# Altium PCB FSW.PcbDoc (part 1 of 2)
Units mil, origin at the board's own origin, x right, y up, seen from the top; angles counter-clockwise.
Board outline 4340.74 x 2765.94 mil, 4 copper layers (Top Layer, Layer 1, Layer 2, Bottom Layer), stack 63.43 mil thick; 152 components, 72 nets, 476 pads, 391 vias.
Unrouted connection lines stored in the file: 225.
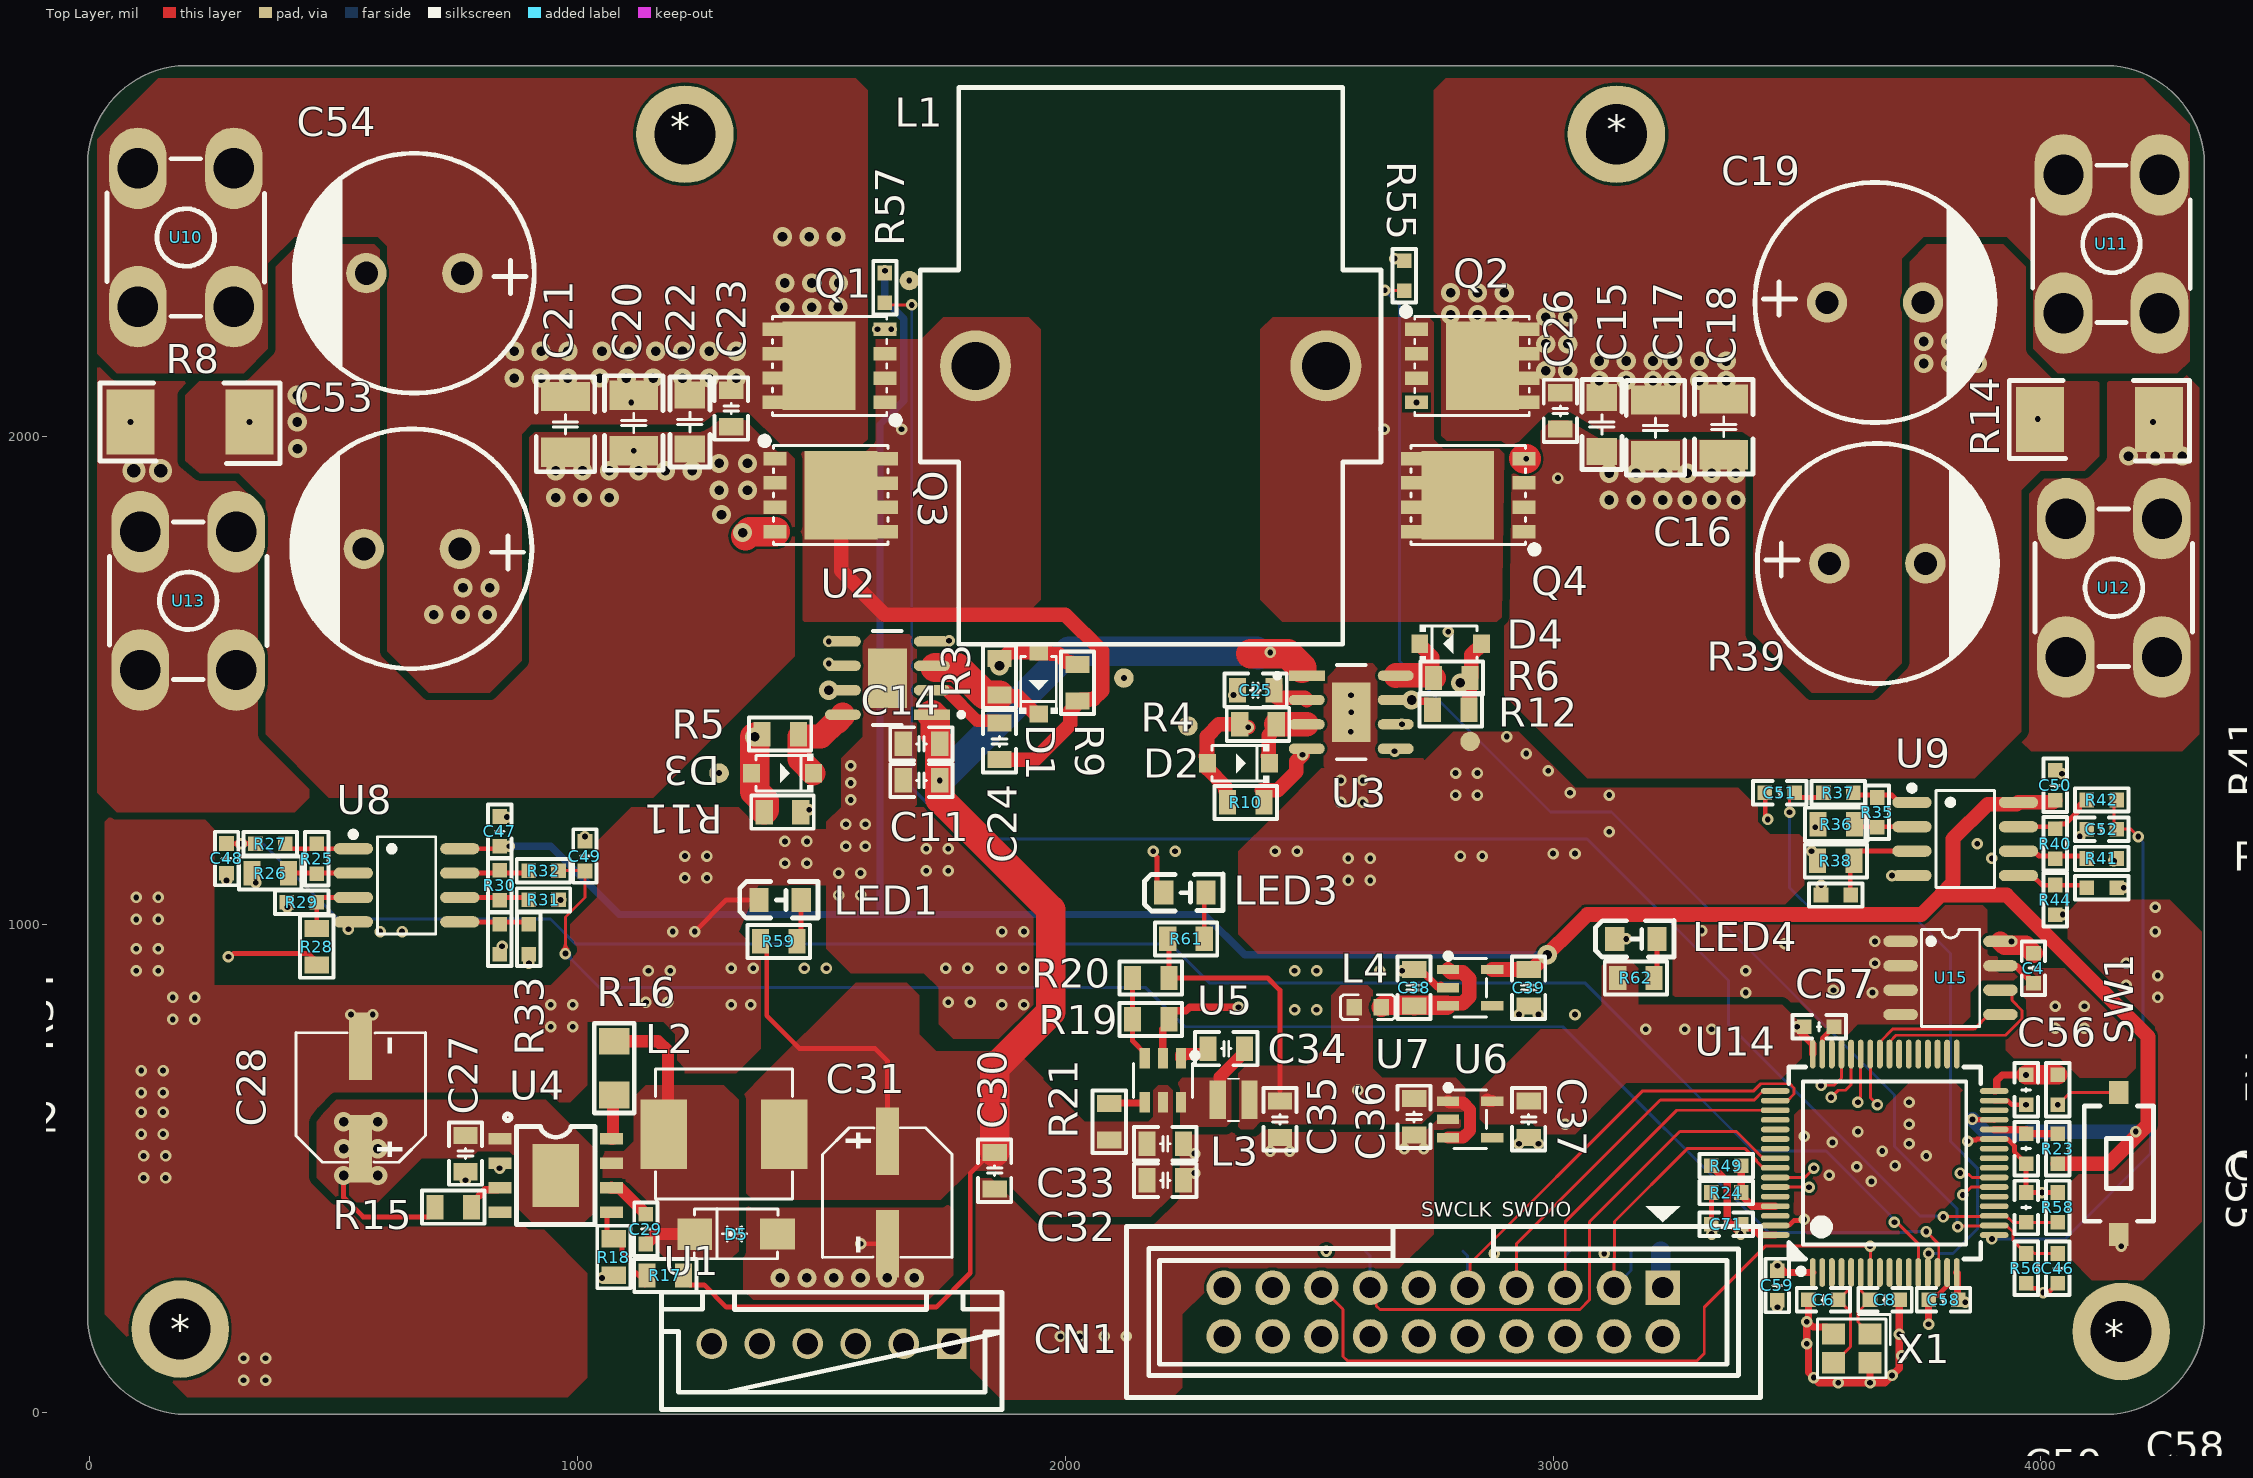
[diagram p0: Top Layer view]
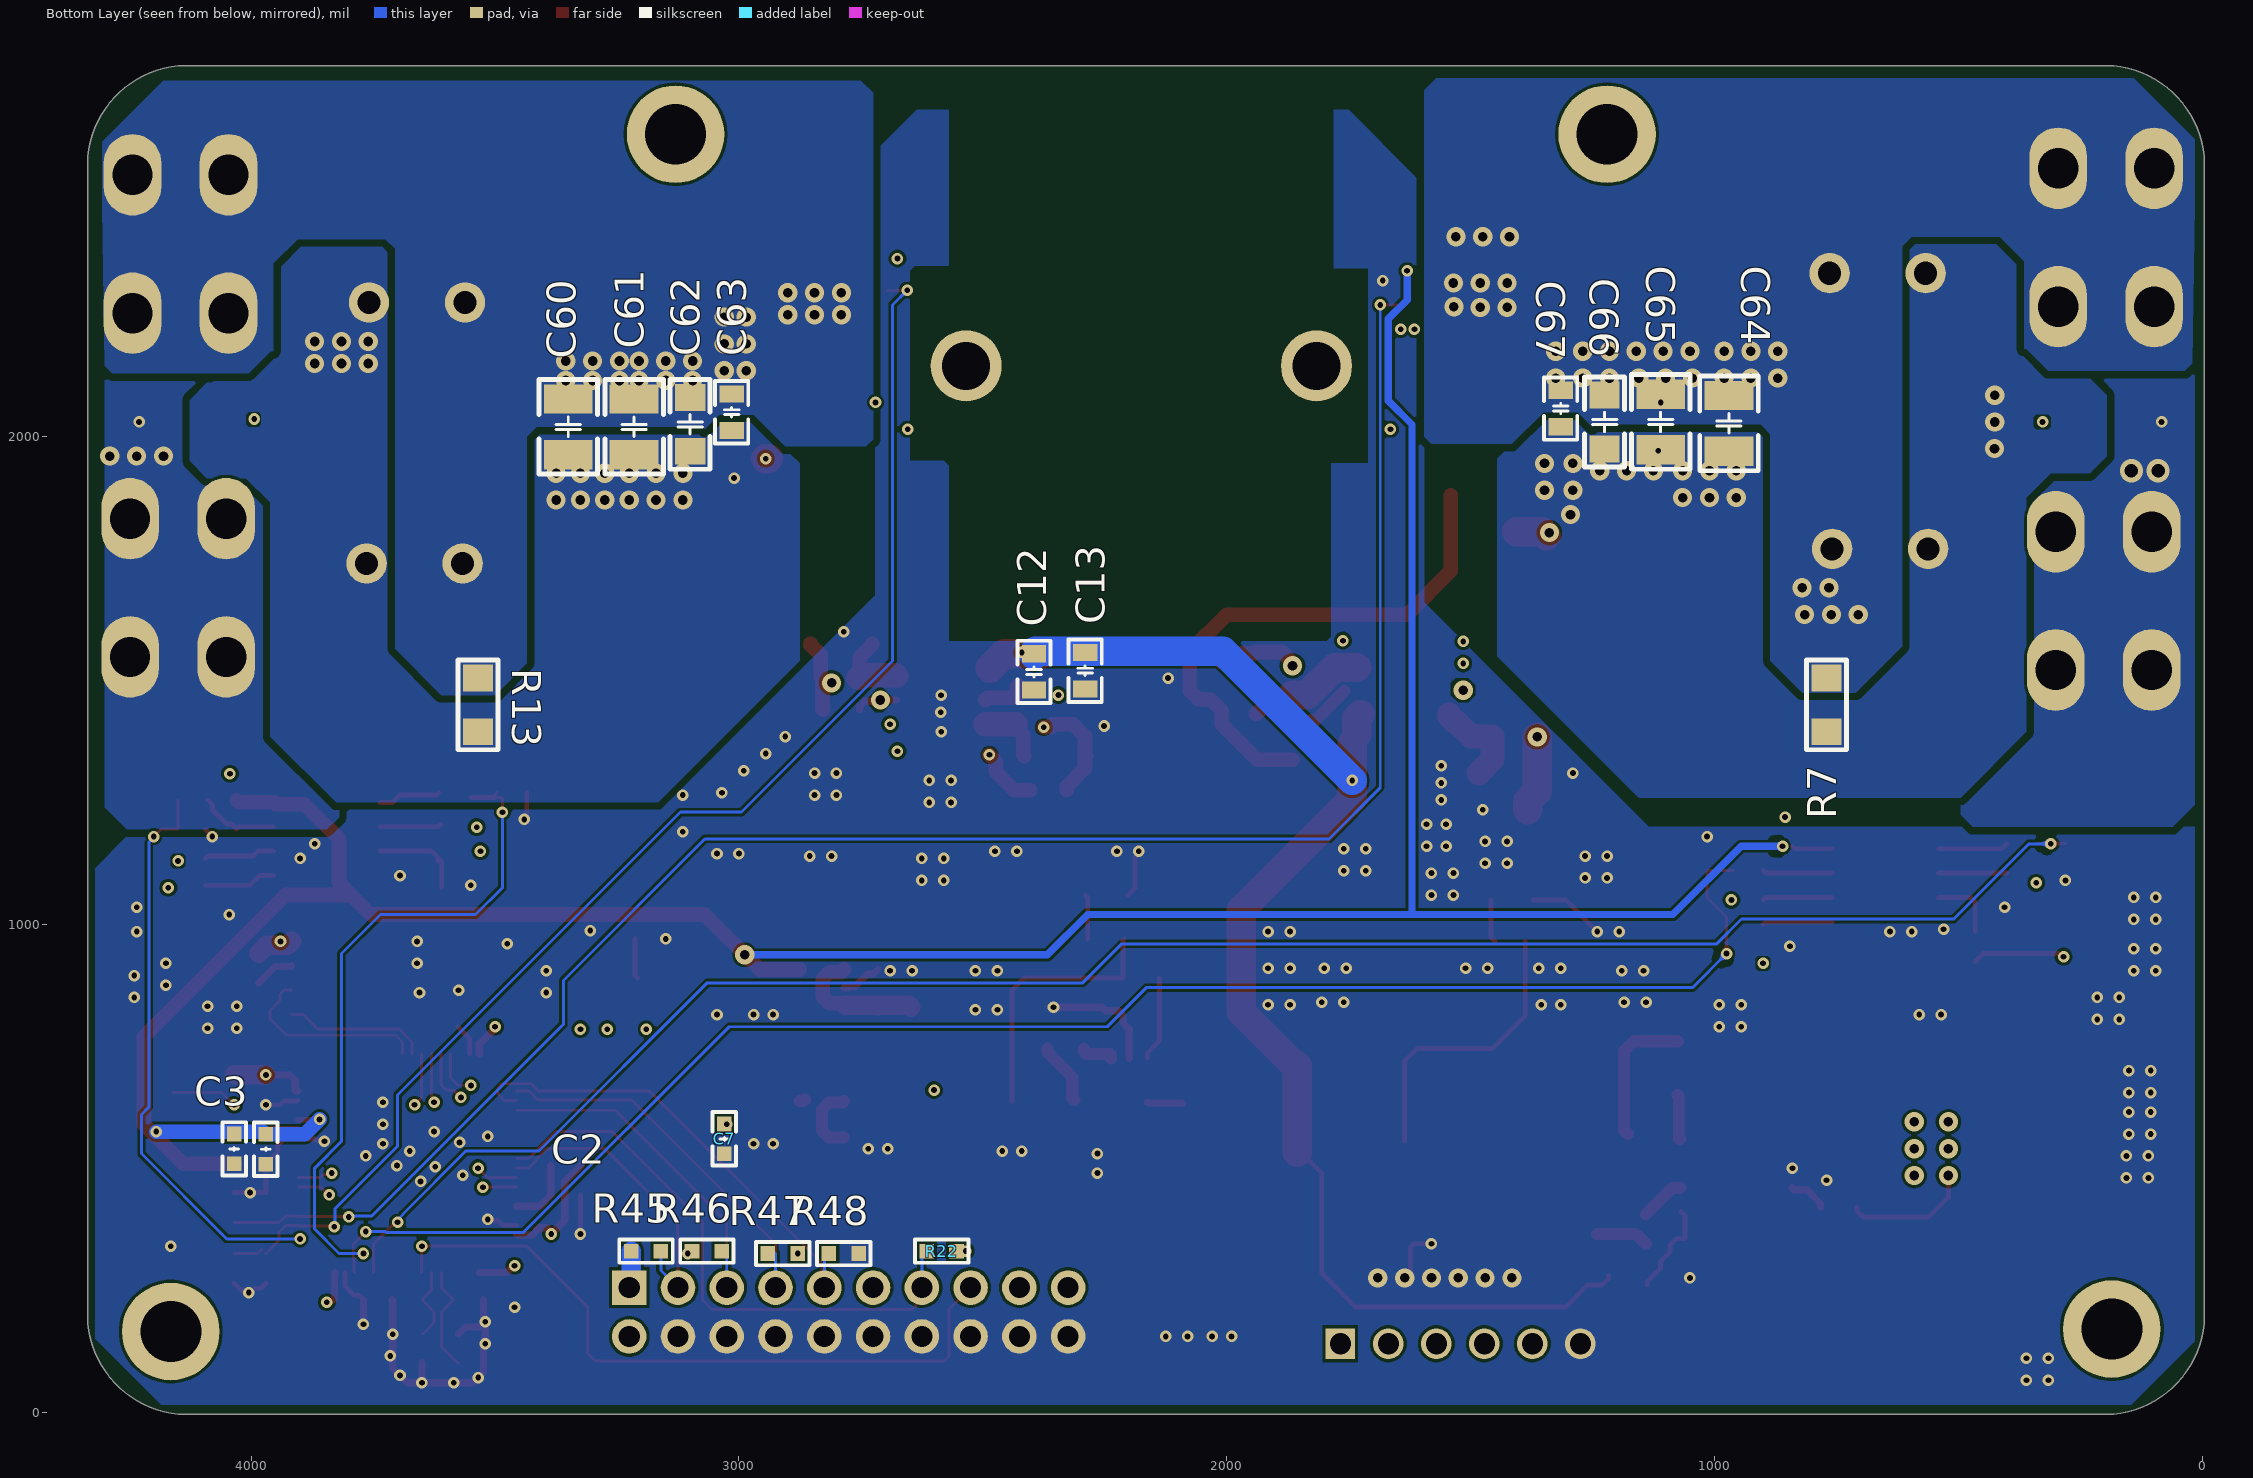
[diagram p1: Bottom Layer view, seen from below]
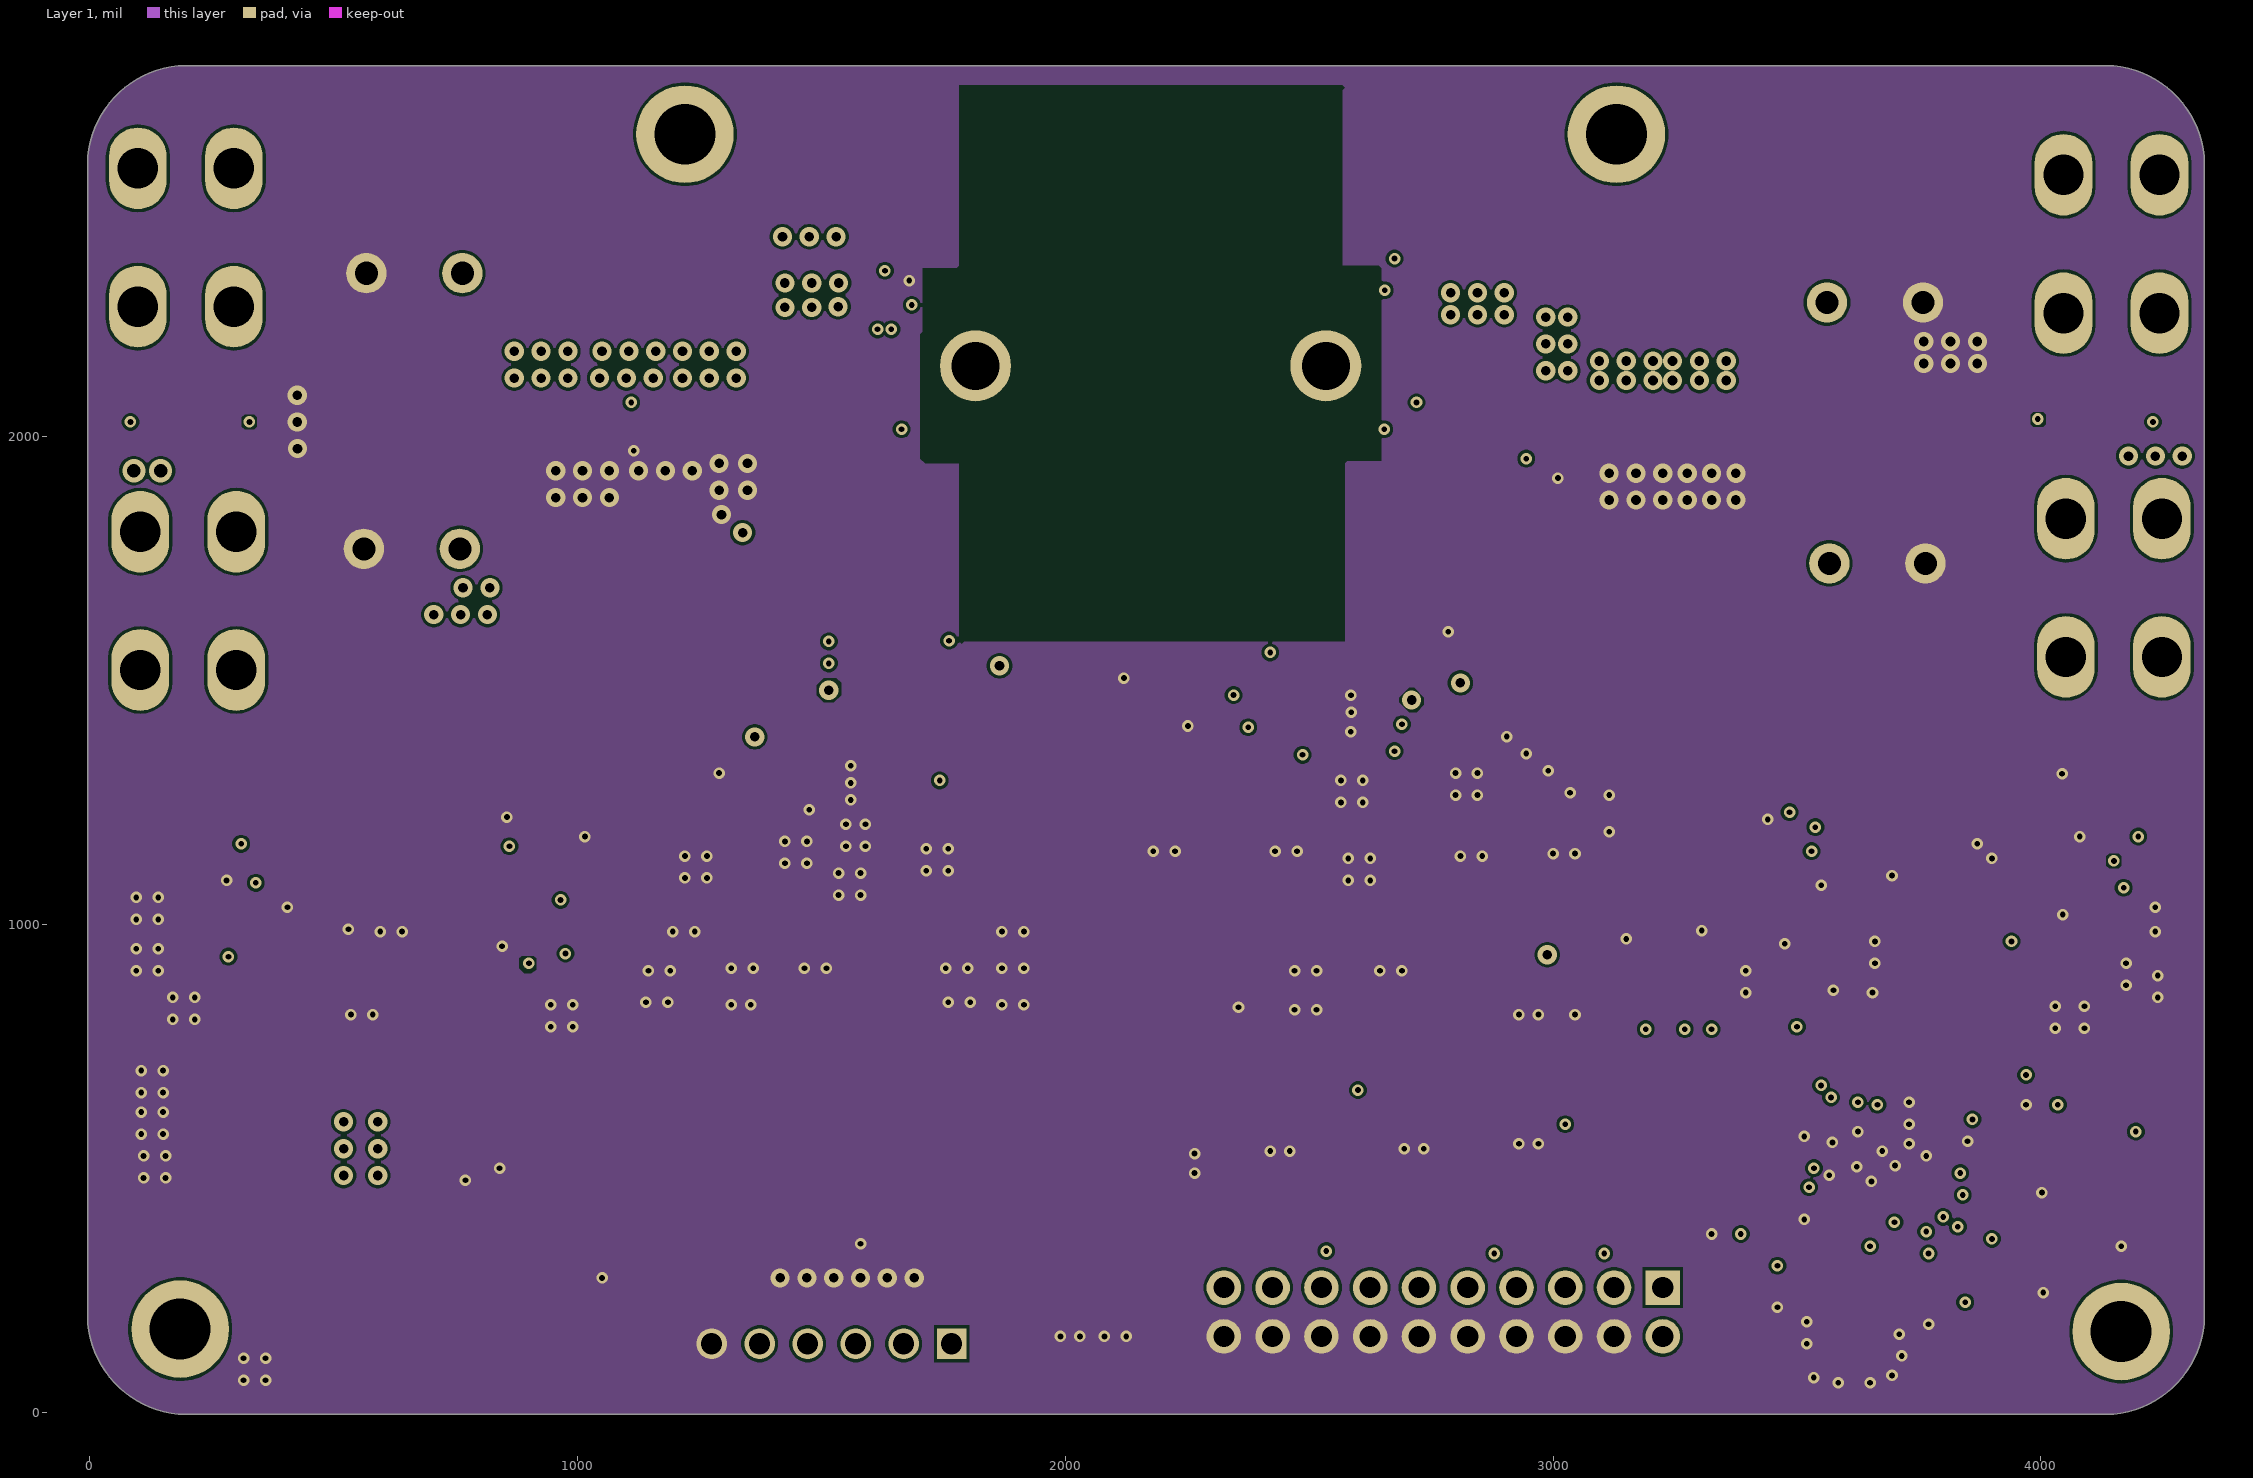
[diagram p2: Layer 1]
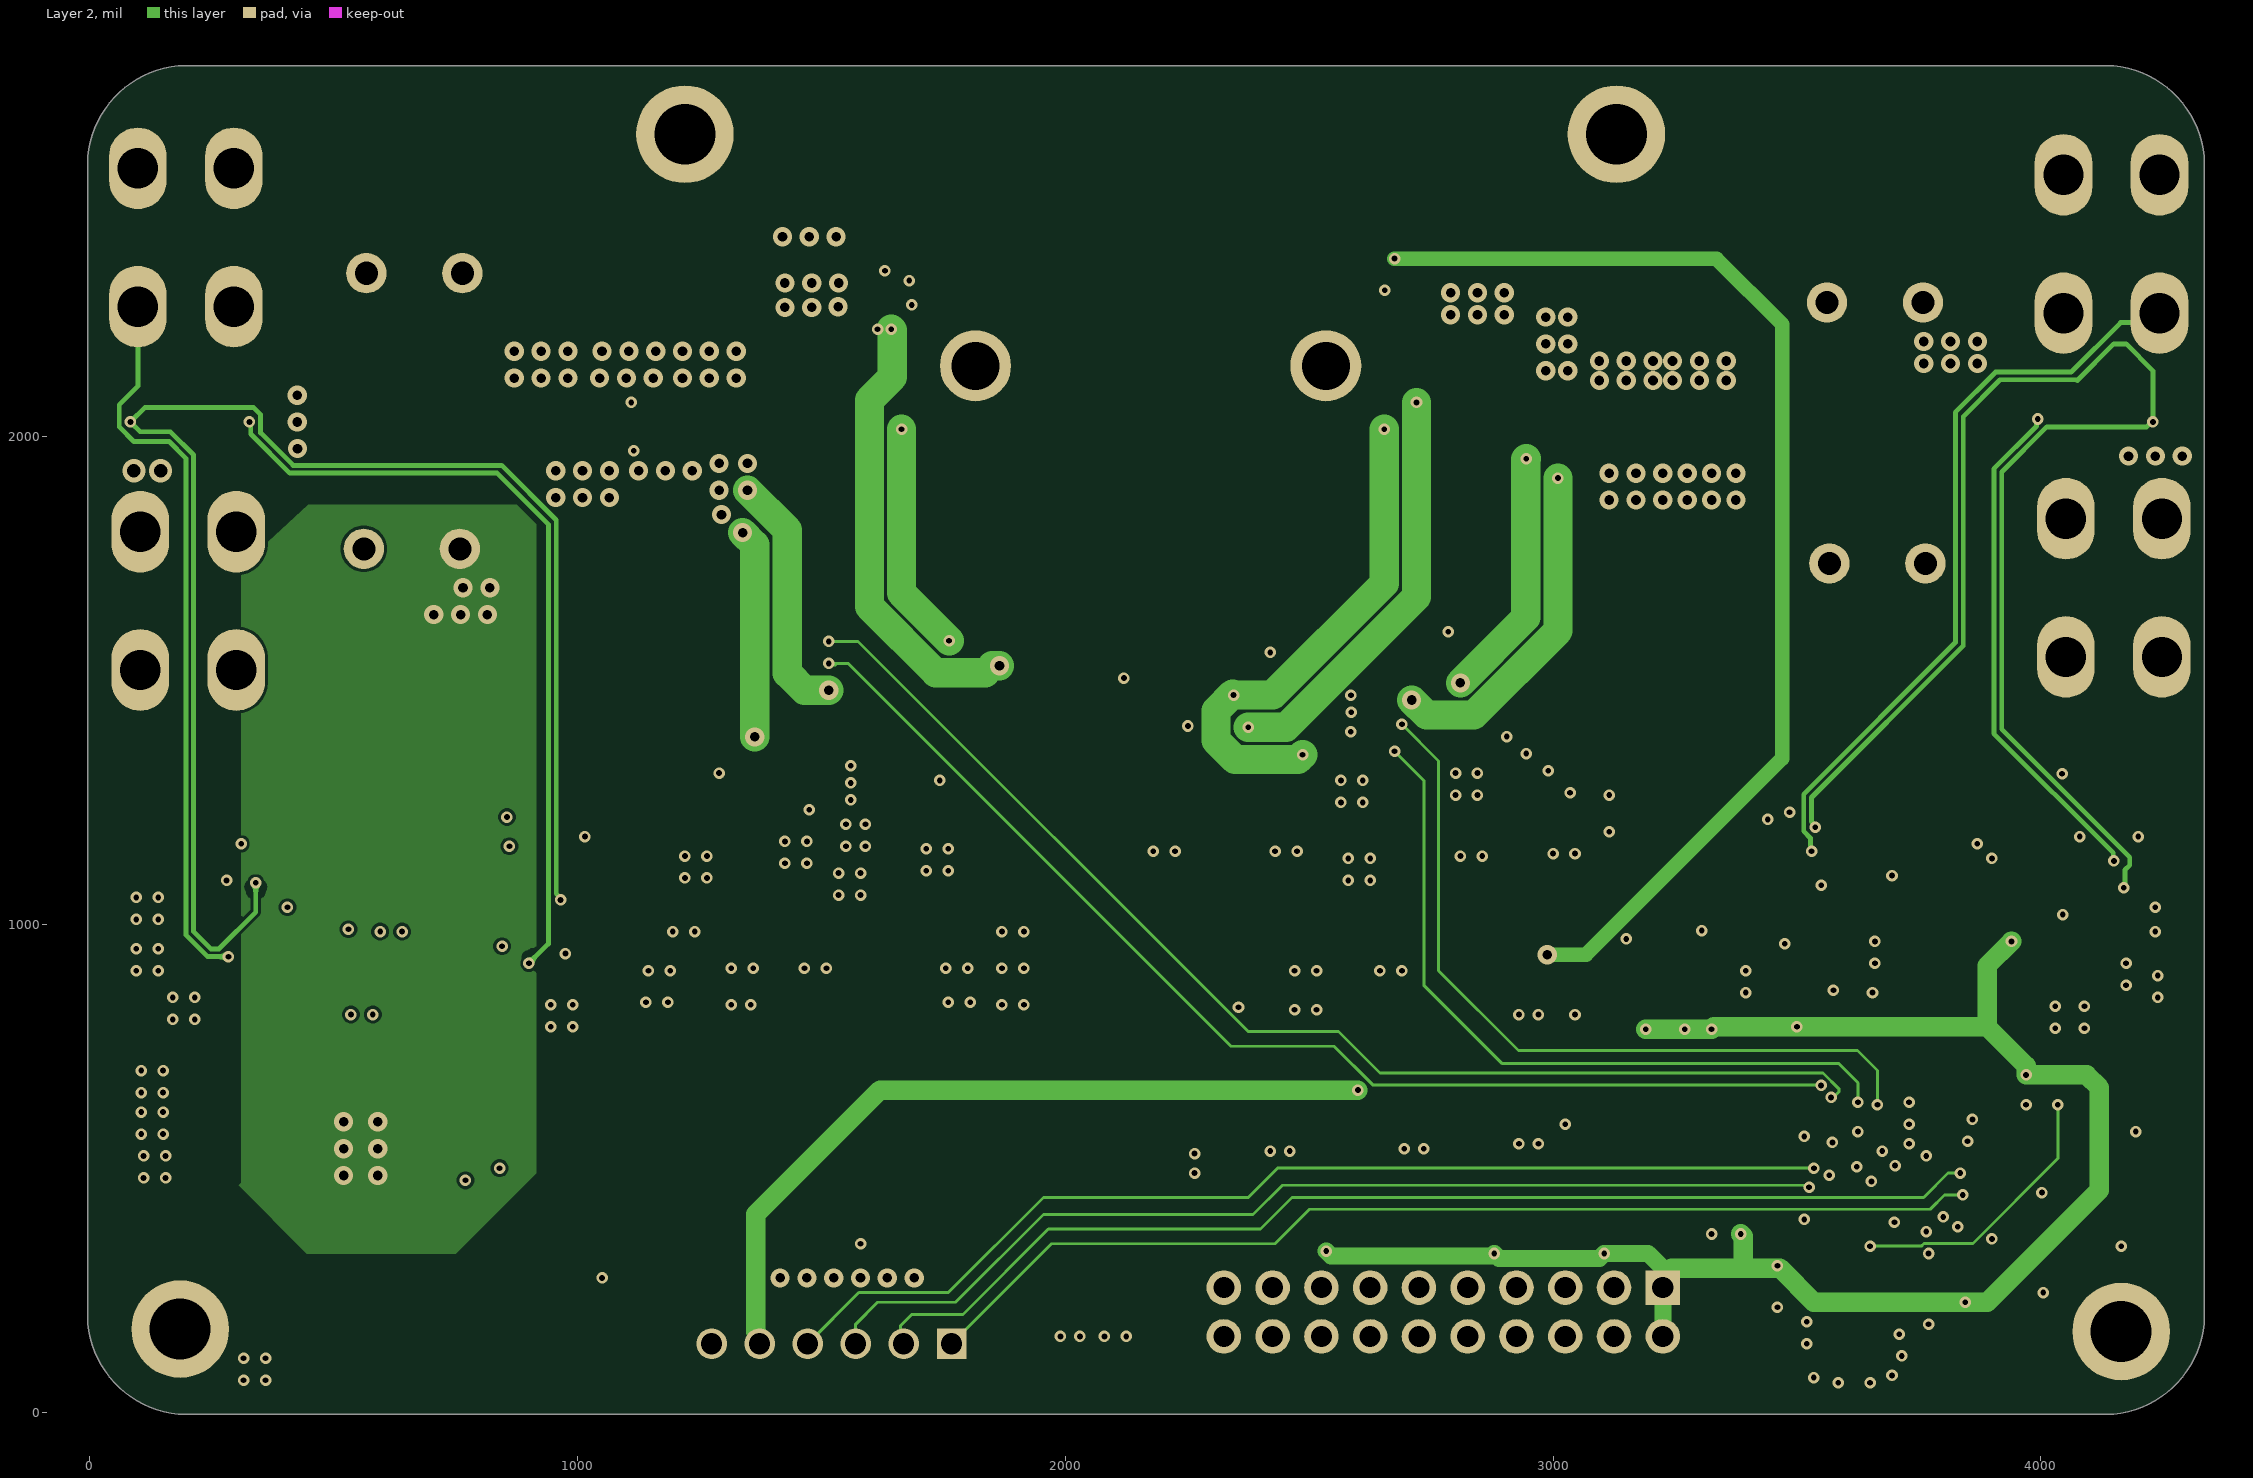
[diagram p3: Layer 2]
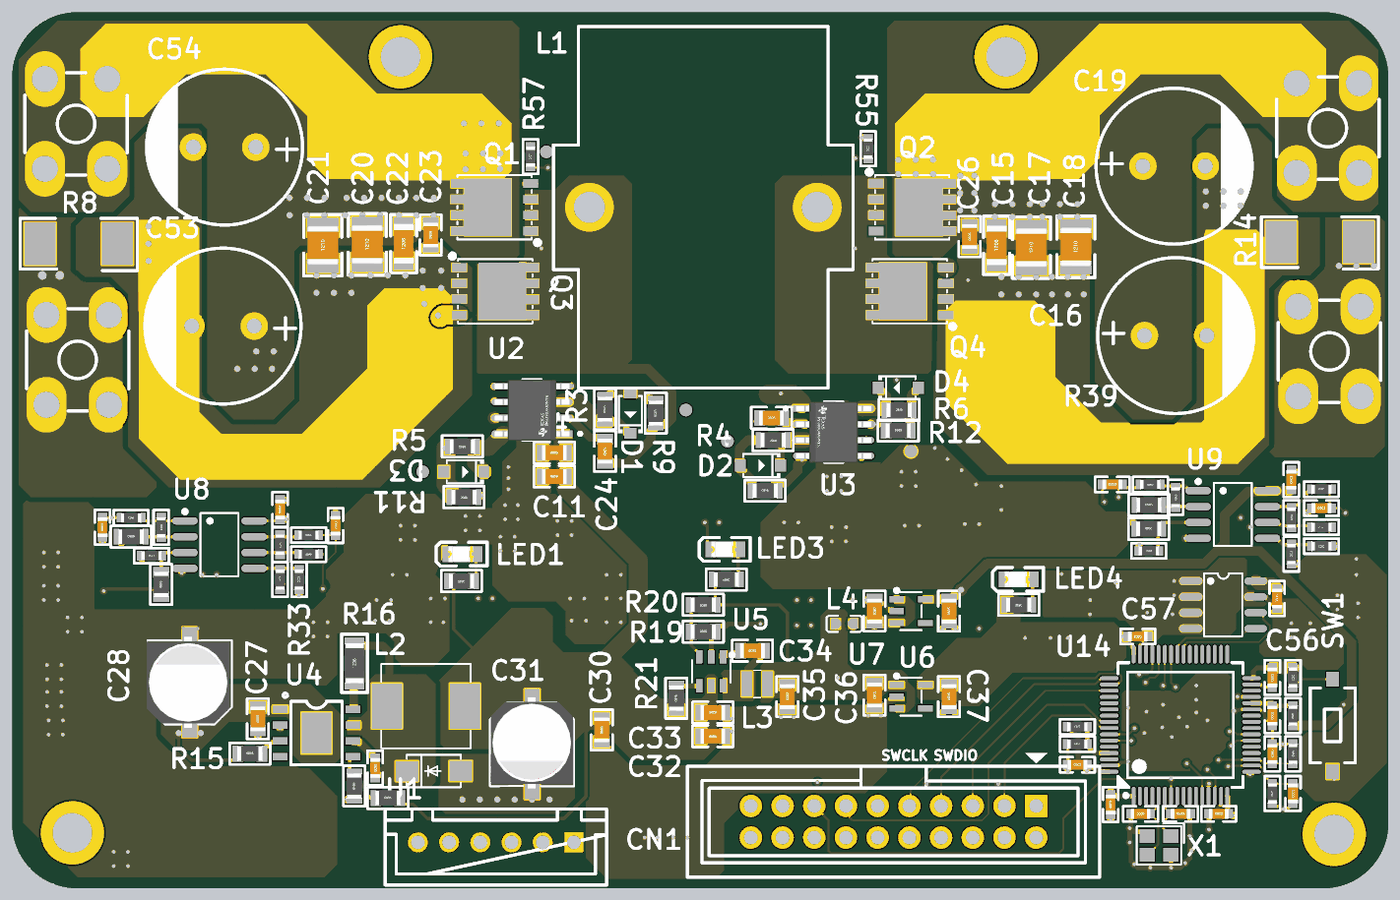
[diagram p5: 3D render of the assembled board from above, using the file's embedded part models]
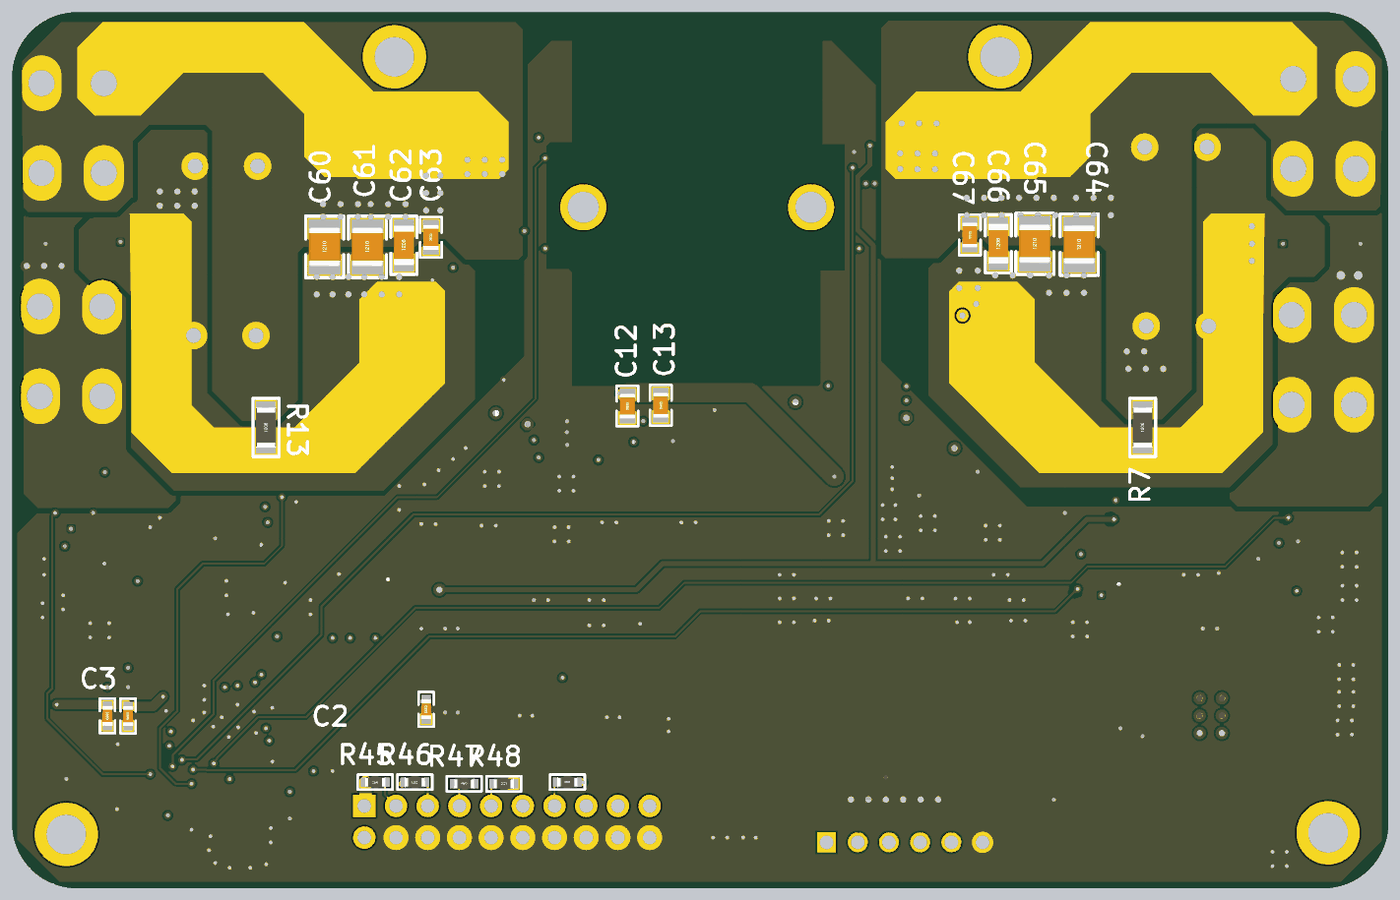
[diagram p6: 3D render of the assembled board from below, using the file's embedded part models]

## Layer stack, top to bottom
Top Solder: solder mask 0.4, Solder Resist, Dk 3.5
Top Layer: signal copper 1.4
Dielectric 2: prepreg 7.0866, PP-006, Dk 4.1
Layer 1: signal copper 1.378
Dielectric 1: dielectric 43.7008, FR-4, Dk 4.8
Layer 2: signal copper 1.378
Dielectric 3: prepreg 7.0866, PP-006, Dk 4.1
Bottom Layer: signal copper 1.4
Bottom Solder: solder mask 0.4, Solder Resist, Dk 3.5

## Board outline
196.27,-4.98 cw(c200,200) -4.98,196.27 -5.01,196.85 -5.01,2559.06 -4.98,2559.64 cw(c200,2555.91) 196.27,2760.89 196.85,2760.92 4133.86,2760.92 4134.44,2760.89 cw(c4130.71,2555.91) 4335.69,2559.64 4335.72,2559.06 4335.72,196.85 4335.69,196.27 cw(c4130.71,200) 4134.44,-4.98 4133.86,-5.01

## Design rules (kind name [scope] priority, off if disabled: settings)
Clearance [All] p1: gap=6 ignorepadtopadclearanceinfootprint=FALSE except(0: Arc-Hole Track-Hole SMDPad-Hole THPad-Hole Via-Hole Fill-Hole Poly-Hole Region-Hole Text-Hole; 10: Arc-Text Track-Text SMDPad-Text THPad-Text Via-Text Fill-Text Poly-Text Region-Text Text-Text; 15.75: Fill-Fill Fill-Poly Fill-Region Poly-Poly Poly-Region Region-Region)
HoleSize [All] p1: absolutevalues=TRUE maxlimit=3937.01 minlimit=1 maxpercent=80.000 minpercent=20.000
MinimumSolderMaskSliver [All] p1: minsoldermaskwidth=4
PolygonConnect [All] p1: connectstyle=Direct reliefconductorwidth=10 reliefentries=4 polygonreliefangle="90 Angle" airgapwidth=10
RoutingVias [All] p1: holewidth=11.81 width=23.62 viastyle="Through Hole" minholewidth=11.81 minwidth=23.62 maxholewidth=28 maxwidth=50
SilkToSolderMaskClearance [IsPad] p1: minsilkscreentomaskgap=4 clearancetoexposedcopper=TRUE
SolderMaskExpansion [All] p1: expansion=4 istentingtop=FALSE
Width [All] p1: maxlimit=100 minlimit=6 preferedwidth=10 minimp=50.000000 maximp=50.000000 favimp=50.000000
27 further rules are at their usual default settings.

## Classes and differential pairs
component class NTC: C46 C55 R55 R56 R57 R58
component class sense: C47 C48 C49 C50 C51 C52 R25 R26 R27 R28 R29 R30 R31 R32 R33 R34 R35 R36 R37 R38 R39 R40 R41 R42 R43 R44 U8 U9
component class "auxiliary power supply": +12v C27 C28 C29 C30 C31 C32 C33 C34 C35 C36 C37 C38 C39 D5 L2 L3 L4 LED1 LED3 LED4 R15 R16 R17 R18 R19 R20 R21 R59 R61 R62 U4 U5 U6 U7
component class power: C11 C12 C13 C14 C15 C16 C17 C18 C19 C20 C21 C22 C23 C24 C25 C26 C53 C54 C60 C61 C62 C63 C64 C65 C66 C67 D1 D2 D3 D4 L1 Q1 Q2 Q3 Q4 R3 R4 R5 R6 R7 R8 R9 R10 R11 R12 R13 R14 U2 U3 U10 U11 U12 U13
component class FSW: * C1 C2 C3 C4 C6 C7 C8 C56 C57 C58 C59 C71 CN1 R1 R22 R23 R24 R45 R46 R47 R48 R49 SW1 U1 U14 U15 X1

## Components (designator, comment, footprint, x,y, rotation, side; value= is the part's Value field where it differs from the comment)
* "M3" "M3 125X200" 3130,2620 r0 top
* "M3" "M3 125X200" 185,170 r0 top
* "M3" "M3 125X200" 1220,2620 r0 top
* "M3" "M3 125X200" 4165,165 r0 top
C1 "2.2uF" "C 0603_L" 3970,540 r90 top
C2 "100nF" "C 0603_L" 3970,538.82 r90 bottom
C3 "4.7uF" "C 0603_L" 4035,539.41 r90 bottom
C4 "100nF" "C 0603_L" 3985,910 r90 top
C6 "20pF" "C 0603_L" 3554.41,230 r0 top
C7 "4.7uF" "C 0603_L" 3030,560 r90 bottom
C8 "20pF" "C 0603_L" 3680.59,230 r0 top
C11 "10uF" "C 0805_L" 1705,1295 r0 top
C12 "100nF" "C 0805_L" 2395,1517.4 r90 bottom
C13 "10uF" "C 0805_L" 2290,1520 r90 bottom
C14 "100nF" "C 0805_L" 1705,1370 r0 top
C15 "1uF" "C 1206_L" 3100,2024.89 r90 top
C16 "100yxj220m12.5x25" CAP-TH_BD12.5-P5.00-D0.6-FD 3665,1740 r0 top value=220uF
C17 "4.7uF" "C 1210_L" 3210,2017.91 r90 top
C18 "4.7uF" "C 1210_L" 3350,2020 r90 top
C19 "100yxj220m12.5x25" CAP-TH_BD12.5-P5.00-D0.6-FD 3660,2275 r0 top value=220uF
C20 "4.7uF" "C 1210_L" 1115,2027.91 r90 top
C21 "4.7uF" "C 1210_L" 975,2025 r90 top
C22 "1uF" "C 1206_L" 1230,2029.89 r90 top
C23 "100nF" "C 0805_L" 1315,2057.6 r90 top
C24 "100nF" "C 0805_L" 1865,1375 r90 top
C25 "100nF" "C 0805_L" 2390,1480 r0 top
C26 "100nF" "C 0805_L" 3015,2052.6 r90 top
C27 "100nF" "C 0805_L" 770,530 r90 top
C28 "jvj100v22m6x8" CAP-SMD_BD6.3-L6.6-W6.6-LS7.3-FD-H7.7 555,645 r90 top value=22uF
C29 "100nF" "C 0603_L" 1140,375 r270 top
C30 "100nF" "C 0805_L" 1855,495 r90 top
C31 "ma25v220m6x8" CAP-SMD_BD6.3-L6.6-W6.6-LS7.3-FD 1635,450 r270 top value=220uF
C32 "4.7uF" "C 0805_L" 2205,550 r180 top
C33 "100nF" "C 0805_L" 2205,475 r180 top
C34 "100nF" "C 0805_L" 2330,745 r180 top
C35 "22uF" "C 0805_L" 2440,600 r270 top
C36 "4.7uF" "C 0805_L" 2715,605 r90 top
C37 "4.7uF" "C 0805_L" 2950,600 r90 top
C38 "4.7uF" "C 0805_L" 2715,870 r270 top
C39 "4.7uF" "C 0805_L" 2950,870 r90 top
C46 "100nF" "C 0603_L" 4035,294.41 r90 top
C47 "470nF" "C 0603_L" 840,1190.59 r90 top
C48 "330pF" "C 0603_L" 280,1135 r90 top
C49 "330pF" "C 0603_L" 1015,1140 r270 top
C50 "470nF" "C 0603_L" 4030,1285 r90 top
C51 "330pF" "C 0603_L" 3465,1270 r0 top
C52 "330pF" "C 0603_L" 4125,1195 r0 top
C53 "100yxj220m12.5x25" CAP-TH_BD12.5-P5.00-D0.6-FD 660,1770 r180 top value=220uF
C54 "100yxj220m12.5x25" CAP-TH_BD12.5-P5.00-D0.6-FD 665,2335 r180 top value=220uF
C55 "100nF" "C 0603_L" 3970,419.41 r270 top
C56 "100nF" "C 0603_L" 3970,660.59 r90 top
C57 "100nF" "C 0603_L" 3545.59,790 r180 top
C58 "100nF" "C 0603_L" 3800.59,230 r0 top
C59 "100nF" "C 0603_L" 3460,259.41 r90 top
C60 "4.7uF" "C 1210_L" 3350,2020 r90 bottom
C61 "4.7uF" "C 1210_L" 3215,2020 r90 bottom
C62 "1uF" "C 1206_L" 3100,2025 r90 bottom
C63 "100nF" "C 0805_L" 3015,2050 r90 bottom
C64 "4.7uF" "C 1210_L" 970,2027.09 r90 bottom
C65 "4.7uF" "C 1210_L" 1110,2030 r90 bottom
C66 "1uF" "C 1206_L" 1225,2030 r90 bottom
C67 "100nF" "C 0805_L" 1315,2057.6 r90 bottom
C71 "100nF" "C 0603_L" 3355,385 r0 top
CN1 "bh254v-20p" CONN-TH_20P-P2.54_BH254V-20P 2775,205 r180 top
D1 "1n4148w_c7420318" SOD-123_L2.7-W1.6-LS3.7-FD 1945,1495 r270 top
D2 "1n4148w_c7420318" SOD-123_L2.7-W1.6-LS3.7-FD 2355,1330 r0 top
D3 "1n4148w_c7420318" SOD-123_L2.7-W1.6-LS3.7-FD 1420,1310 r0 top
D4 "1n4148w_c7420318" SOD-123_L2.7-W1.6-LS3.7-FD 2790,1575 r180 top
D5 "ss310_c7420364" SMA_L4.3-W2.6-LS5.0-FD 1325,365 r180 top
L1 "fc-se2822-150m" IND-TH_L28.0-W23.0_FC-SE2822 2175,2145 r90 top value=15uH
L2 "fxl0630-470-m" IND-SMD_L7.0-W6.6_FXL0630 1300,570 r180 top value=47uH
L3 "ftc252010s4r7mbca" IND-SMD_L2.5-W2.0-VLS252012CX-150M 2345,640 r0 top value=4.7uH
L4 "gz1608d601tf" L0603 2620,830 r0 top
LED1 "ncd0805r1" LED0805-RD 1415,1050 r0 top
LED3 "ncd0805r1" LED0805-RD 2245,1065 r0 top
LED4 "ncd0805r1" LED0805-RD 3170,970 r0 top
Q1 "cjac80sn10" PDFN-8_L5.8-W5.0-P1.27-LS6.0-BL 1516.2,2145 r90 top
Q2 "cjac80sn10" PDFN-8_L5.8-W5.0-P1.27-LS6.0-BL 2834.2,2145 r270 top
Q3 "cjac80sn10" PDFN-8_L5.8-W5.0-P1.27-LS6.0-BL 1519.2,1880 r270 top
Q4 "cjac80sn10" PDFN-8_L5.8-W5.0-P1.27-LS6.0-BL 2825.8,1880 r90 top
R1 "10K" "R 0603_L" 4035,660.59 r270 top
R3 "10R" "R 0805_L" 1865,1507.4 r90 top
R4 "10R" "R 0805_L" 2395,1410 r180 top
R5 "10R" "R 0805_L" 1415,1390 r180 top
R6 "10R" "R 0805_L" 2792.4,1505 r0 top
R7 "10K" "R 1206_L" 770,1450 r90 bottom
R8 "hojlr2512-3w-5mr-1%" RES-SMD_L6.4-W3.2-1 205,2030 r0 top value=5mΩ
R9 "10K" "R 0805_L" 2025,1495 r90 top
R10 "10K" "R 0805_L" 2370,1250 r0 top
R11 "10K" "R 0805_L" 1420,1230 r180 top
R12 "10K" "R 0805_L" 2790,1440 r0 top
R13 "10K" "R 1206_L" 3535,1450 r90 bottom
R14 "hojlr2512-3w-5mr-1%" RES-SMD_L6.4-W3.2-1 4120,2035 r0 top value=5mΩ
R15 "470k" "R 0805_L" 745,420 r0 top
R16 "0.22R" "R 1206_L" 1075,705.12 r90 top
R17 "9.1K" "R 0805_L" 1180,280 r0 top
R18 "1K" "R 0805_L" 1074.24,317.83 r90 top
R19 "15K" "R 0805_L" 2175,805 r0 top
R20 "110k" "R 0805_L" 2175,890 r180 top
R21 "470k" "R 0805_L" 2090,595 r90 top
R22 "10K" "R 0603_L" 2584.41,330 r180 bottom
R23 "0R" "R 0603_L" 4035,540 r90 top
R24 "0R" "R 0603_L" 3355,450 r0 top
R25 "3.74K" "R 0603_L" 465,1134.41 r270 top
R26 "75K" "R 0805_L" 370,1105 r0 top
R27 "100" "R 0603_L" 370,1165 r180 top
R28 "75K" "R 0805_L" 465,954.41 r90 top
R29 "3.74K" "R 0603_L" 434.41,1045 r0 top
R30 "2.0K" "R 0603_L" 840,1080 r270 top
R31 "100" "R 0603_L" 930,1050 r180 top
R32 "100" "R 0603_L" 930,1110 r0 top
R33 "100" "R 0603_L" 900,969.41 r90 top
R34 "2.0K" "R 0603_L" 840,969.41 r90 top
R35 "3.74K" "R 0603_L" 3665,1229.41 r270 top
R36 "75K" "R 0805_L" 3580.59,1205 r0 top
R37 "100" "R 0603_L" 3585,1270 r180 top
R38 "75K" "R 0805_L" 3580,1130 r0 top
R39 "3.74K" "R 0603_L" 3580,1060 r0 top
R40 "2.0K" "R 0603_L" 4030,1165 r270 top
R41 "100" "R 0603_L" 4125,1135 r180 top
R42 "100" "R 0603_L" 4125,1255 r0 top
R43 "100" "R 0603_L" 4125,1075 r180 top
R44 "2.0K" "R 0603_L" 4030,1050 r90 top
R45 "10K" "R 0603_L" 3190.59,330 r0 bottom
R46 "10K" "R 0603_L" 3065.59,330 r0 bottom
R47 "10K" "R 0603_L" 2910,325 r180 bottom
R48 "10K" "R 0603_L" 2785,325 r180 bottom
R49 "0R" "R 0603_L" 3355,505 r0 top
R55 "10K" "R 0603_L" 2695,2330 r90 top
R56 "10K" "R 0603_L" 3970,294.41 r90 top
R57 "10K" "R 0603_L" 1630,2305 r90 top
R58 "10K" "R 0603_L" 4035,419.41 r270 top
R59 "1K" "R 0805_L" 1412.4,965 r180 top
R61 "1K" "R 0805_L" 2247.4,970 r180 top
R62 "1K" "R 0805_L" 3170,890 r180 top
SW1 "ts-1101-c-w" SW-SMD_L6.0-W3.3-LS8.0_TS-1101-C-W 4160,509.33 r90 top
U1 "zx-xh2.54-6pzz" CONN-TH_6P-P2.50_ZX-XH2.54-6PZZ 1520.78,140 r180 top
U2 "UCC27211DDAR" FP-DDA0008E-IPC_C 1635,1505 r180 top
U3 "UCC27211DDAR" FP-DDA0008E-IPC_C 2586.18,1435 r0 top
U4 "eg1192l" ESOP-8_L4.9-W3.9-P1.27-LS6.0-BL-EP 955,485 r270 top
U5 "sy8120b1abc" SOT-23-6_L2.9-W1.6-P0.95-LS2.8-BL 2200,680 r180 top
U6 "rt9013-33gb" SOT-23-5_L3.0-W1.7-P0.95-LS2.8-BL 2830,600 r270 top
U7 "rt9013-33gb" SOT-23-5_L3.0-W1.7-P0.95-LS2.8-BL 2830,870 r270 top
U8 "gs8558-sr" SOIC-8_L4.9-W3.8-P1.27-LS6.0-BL 649.1,1080 r270 top
U9 "gs8558-sr" SOIC-8_L4.9-W3.8-P1.27-LS6.0-BL 3845,1175 r270 top
U10 "t34001" CONN-TH_T34001 196.58,2408.27 r0 top
U11 "t34001" CONN-TH_T34001 4145,2395 r0 top
U12 "t34001" CONN-TH_T34001 4150,1690 r0 top
U13 "t34001" CONN-TH_T34001 201.58,1663.27 r0 top
U14 "stm32g474rbt3" LQFP-64_L10.0-W10.0-P0.50-LS12.0-BL 3680,510 r0 top
U15 "at24c512c-sshd-t" SOIC-8_L4.9-W3.9-P1.27-LS6.0-BL 3815,890 r270 top
X1 "x252024mob4si" CRYSTAL-SMD_4P-L2.5-W2.0-BL 3612.4,130.47 r180 top value=24MHz

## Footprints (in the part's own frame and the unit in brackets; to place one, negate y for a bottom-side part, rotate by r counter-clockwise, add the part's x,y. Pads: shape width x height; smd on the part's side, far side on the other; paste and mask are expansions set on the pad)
"C 0603_L" [mil] "无极性贴片电容"
  rect 30x30 smd: 1(-30.59,0) 2(30.59,0)
  silkscreen extent -55,-24 55,24, body extent -31,-16 31,16, height 32
"C 0805_L" [mil] "无极性贴片电容"
  rect 35x50 smd: 1(-37.4,0) 2(37.4,0)
  silkscreen extent -64,-34 64,34, body extent -39,-24 39,24, height 20
"C 1206_L" [mil] "无极性贴片电容"
  rect 55x62 smd: 1(-55.12,0) 2(55.11,0)
  silkscreen extent -92,-41 92,41, body extent -63,-32 63,32, height 48
"C 1210_L" [mil] "无极性贴片电容"
  rect 60x100 smd: 1(-57.09,0) 2(57.09,0)
  silkscreen extent -97,-60 97,60, body extent -63,-51 63,51, height 60
CAP-SMD_BD6.3-L6.6-W6.6-LS7.3-FD [mil]
  rect 137.8x47.2 smd: 1(-105.1,0) 2(105.1,0)
  silkscreen extent -133,-133 133,133, body extent -148,-131 140,129, height 228
CAP-SMD_BD6.3-L6.6-W6.6-LS7.3-FD-H7.7 [mil]
  rect 137.8x47.2 smd: 1(-105.1,0) 2(105.1,0)
  silkscreen extent -133,-133 133,133, body extent -144,-125 144,135, height 228
CAP-TH_BD12.5-P5.00-D0.6-FD [mm]
  round 2.1 hole 1.2 paste-2539.97 mask+0.05: 1(-2.5,0) 2(2.5,0)
  silkscreen extent -6.25,-6.25 6.25,6.25
CONN-TH_6P-P2.50_ZX-XH2.54-6PZZ [mm]
  rect 1.524x1.6 hole 1.1 paste-2539.97 mask+0.051: 1(-6.25,0)
  round 1.6 hole 1.1 copper offset 0,0 paste-2539.97 mask+0.051: 2(-3.75,0) 4(1.25,0) 5(3.75,0) 6(6.25,0)
  round 1.6 hole 1.1 paste-2539.97 mask+0.051: 3(-1.25,0)
  silkscreen extent -8.87,-2.68 8.87,3.42
CONN-TH_20P-P2.54_BH254V-20P [mm]
  rect 1.8x1.8 hole 1.1: 1(-11.43,-1.27)
  round 1.8 hole 1.1: 2(-11.43,1.27) 3(-8.89,-1.27) 4(-8.89,1.27) 5(-6.35,-1.27) 6(-6.35,1.27) 7(-3.81,-1.27) 8(-3.81,1.27) 9(-1.27,-1.27) 10(-1.27,1.27) 11(1.27,-1.27) 12(1.27,1.27) 13(3.81,-1.27) 14(3.81,1.27) 15(6.35,-1.27) 16(6.35,1.27) 17(8.89,-1.27) 18(8.89,1.27) 19(11.43,-1.27) 20(11.43,1.27)
  silkscreen extent -16.51,-5.51 16.51,4.45
CONN-TH_T34001 [mm]
  oval 3x4.25 hole 2.1: 1(-2.5,-3.6) 2(2.5,-3.6) 3(2.5,3.6) 4(-2.5,3.6)
  silkscreen extent -4.1,-4.1 4.1,4.1
CRYSTAL-SMD_4P-L2.5-W2.0-BL [mm]
  rect 1.2x1.1 smd: 1(-0.95,-0.75) 2(0.95,-0.75) 3(0.95,0.75) 4(-0.95,0.75)
  silkscreen extent -2.01,-1.76 1.78,1.53
ESOP-8_L4.9-W3.9-P1.27-LS6.0-BL-EP [mil]
  rect 23.6x47.2 smd: 1(-75,-114.5) 2(-25,-114.5) 3(25,-114.5) 4(75,-114.5) 5(75,114.5) 6(25,114.5) 7(-25,114.5) 8(-75,114.5)
  rect 129.9x94.5 smd: 9(0,0)
  silkscreen extent -126,-105 100,81
FP-DDA0008E-IPC_C [mm]
  rect 1.874x0.542 smd: 1(-2.316,1.905)
  rrect100% 1.874x0.542 smd: 2(-2.316,0.635) 3(-2.316,-0.635) 4(-2.316,-1.905) 5(2.316,-1.905) 6(2.316,-0.635) 7(2.316,0.635) 8(2.316,1.905)
  rect 2.025x3.1 smd: 9(0,0)
  silkscreen extent -3.98,-2.45 0.75,2.45, body extent -3.35,-2.55 3.35,2.55, height 0.25
IND-SMD_L2.5-W2.0-VLS252012CX-150M [mm]
  rect 0.85x2 smd: 1(-0.83,0) 2(0.83,0)
  silkscreen extent -0.29,-1.1 0.29,1.1
IND-SMD_L7.0-W6.6_FXL0630 [mil]
  rect 95.4x142.5 smd: 1(123.1,0) 2(-123.2,0)
  silkscreen extent -141,-133 141,133
IND-TH_L28.0-W23.0_FC-SE2822 [mm]
  round 3.7 hole 2.5: 1(0,9.125) 2(0,-9.125)
  silkscreen extent -14.5,-12 14.5,12
L0603 [mil]
  rect 31.5x34 smd paste-3937 mask+2: 1(-27.6,0) 2(27.5,0)
  silkscreen extent -56,-26 56,26
LED0805-RD [mm]
  rect 1x1.25 smd: 1(-1.1,0) 2(1.1,0)
  silkscreen extent -2.1,-0.95 1.98,0.96, body extent -1.14,-0.63 0.88,0.64, height 1
LQFP-64_L10.0-W10.0-P0.50-LS12.0-BL [mm]
  oval 0.3x1.5 smd: 1(-3.75,-5.688) 2(-3.25,-5.688) 3(-2.75,-5.688) 4(-2.25,-5.688) 5(-1.75,-5.688) 6(-1.25,-5.688) 7(-0.75,-5.688) 8(-0.25,-5.688) 9(0.25,-5.688) 10(0.75,-5.688) 11(1.25,-5.688) 12(1.75,-5.688) 13(2.25,-5.688) 14(2.75,-5.688) 15(3.25,-5.688) 16(3.75,-5.688) 33(3.75,5.688) 34(3.25,5.688) 35(2.75,5.688) 36(2.25,5.688) 37(1.75,5.688) 38(1.25,5.688) 39(0.75,5.688) 40(0.25,5.688) 41(-0.25,5.688) 42(-0.75,5.688) 43(-1.25,5.688) 44(-1.75,5.688) 45(-2.25,5.688) 46(-2.75,5.688) 47(-3.25,5.688) 48(-3.75,5.688)
  oval 1.5x0.3 smd: 17(5.7,-3.738) 18(5.7,-3.238) 19(5.7,-2.738) 20(5.7,-2.238) 21(5.7,-1.738) 22(5.7,-1.238) 23(5.7,-0.738) 24(5.7,-0.238) 25(5.7,0.262) 26(5.7,0.762) 27(5.7,1.262) 28(5.7,1.762) 29(5.7,2.262) 30(5.7,2.762) 31(5.7,3.262) 32(5.7,3.762) 49(-5.7,3.762) 50(-5.7,3.262) 51(-5.7,2.762) 52(-5.7,2.262) 53(-5.7,1.762) 54(-5.7,1.262) 55(-5.7,0.762) 56(-5.7,0.262) 57(-5.7,-0.238) 58(-5.7,-0.738) 59(-5.7,-1.238) 60(-5.7,-1.738) 61(-5.7,-2.238) 62(-5.7,-2.738) 63(-5.7,-3.238) 64(-5.7,-3.738)
  silkscreen extent -5,-5.78 5,5.01
"M3 125X200" [mil] "M3螺丝孔，孔125Mil，焊盘200Mil"
  round 200 hole 125: 1(0,0)
PDFN-8_L5.8-W5.0-P1.27-LS6.0-BL [mil]
  rect 27.6x47.2 smd paste-3937 mask+2: 1(-75,-114.2) 2(-25,-114.2) 3(25,-114.2) 4(75,-114.2) 5(74.8,114.1) 6(25.2,114.1) 7(-24.8,114.1) 8(-74.8,114.1)
  rect 181.1x149.6 smd paste-3937 mask+2: 9(0,21.2)
  silkscreen extent -116,-141 102,117
"R 0603_L" [mil] "1/10W贴片电阻"
  rect 30x30 smd: 1(-30.59,0) 2(30.59,0)
  silkscreen extent -55,-24 55,24, body extent -31,-16 32,16, height 16
"R 0805_L" [mil] "1/8W贴片电阻"
  rect 35x50 smd: 1(-37.4,0) 2(37.4,0)
  silkscreen extent -64,-34 64,34, body extent -39,-25 39,25, height 20
"R 1206_L" [mil] "1/4W贴片电阻"
  rect 55x62 smd: 1(-55.12,0) 2(55.11,0)
  silkscreen extent -92,-41 92,41, body extent -63,-31 63,31, height 22
RES-SMD_L6.4-W3.2-1 [mil]
  rect 98.4x133.9 smd: 1(-122,0) 2(122.1,0)
  silkscreen extent -184,-85 185,80
SMA_L4.3-W2.6-LS5.0-FD [mil]
  rect 70.9x63.8 smd: 1(-84.7,-0.3) 2(84.6,0.4)
  silkscreen extent -86,-52 86,51
SOD-123_L2.7-W1.6-LS3.7-FD [mil]
  rect 34.6x37.8 smd: 1(-63.4,0) 2(63.4,0)
  silkscreen extent -54,-39 63,39
SOIC-8_L4.9-W3.8-P1.27-LS6.0-BL [mil]
  oval 23.1x80.5 smd: 1(-75,-109.1) 2(-25,-109.1) 3(25,-109.1) 4(75,-109.1) 5(75,109.2) 6(25,109.2) 7(-25,109.2) 8(-75,109.2)
  silkscreen extent -110,-115 100,60
SOIC-8_L4.9-W3.9-P1.27-LS6.0-BL [mm]
  oval 0.588x1.8 smd paste+0 mask+0.051: 1(-1.905,-2.6) 2(-0.635,-2.6) 3(0.635,-2.6) 4(1.905,-2.6) 5(1.905,2.6) 6(0.635,2.6) 7(-0.635,2.6) 8(-1.905,2.6)
  silkscreen extent -2.53,-1.52 2.53,1.52
SOT-23-5_L3.0-W1.7-P0.95-LS2.8-BL [mil]
  rect 19.3x45.6 smd: 1(-37.4,-45.4) 2(0,-45.4) 3(37.4,-45.4)
  rect 19.3x46.3 smd: 4(37.4,45.5) 5(-37.4,45.5)
  silkscreen extent -71,-51 60,34
SOT-23-6_L2.9-W1.6-P0.95-LS2.8-BL [mil]
  rect 20.9x42.2 smd: 1(-37.4,-45.3) 2(0,-45.3) 3(37.4,-45.3) 4(37.4,45.2) 5(0,45.2) 6(-37.4,45.2)
  silkscreen extent -72,-57 61,35
SW-SMD_L6.0-W3.3-LS8.0_TS-1101-C-W [mm]
  rect 1.2x1 smd: 1(-3.7,0) 2(3.7,0)
  silkscreen extent -3,-1.8 3,1.8

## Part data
* * * *: "铜柱孔"
C1 C6 C8 C46 C49 C55: library part C, "无极性贴片电容"
C2 C4 C56 C57 C58 C59 C71: library part C, "6.3V X7R 0603 100nF"
C3 C7: library part C, "6.3V X7R 0603 4.7uF"
C11 C13: library part C, "25V X7R 0805 10uF"
C12 C14 C24 C25 C29 C30 C33 C34: library part C, "25V X7R 0805 100nF"
C15 C62: library part C, "100V X7R 1206 1uF"
C16 C19 C53 C54: "容值:220uF;精度:±20%;额定电压:100V;纹波电流:1.62A@100kHz;等效串联电阻(ESR):-;", Equivalent Series Resistance(ESR)=-, JLCPCB Part Class="Extended Part", LCSC Part Name="220uF ±20% 100V", Manufacturer=Rubycon(红宝石), ManufacturerPart=100YXJ220M12.5X25, Operating Temperature=-40℃~+105℃, Ripple Current=1.62A@100kHz, Tolerance=±20%, Voltage Rating=100V
C17 C18 C60 C61: library part C, "100V X7R 1210 4.7uF"
C20 C21 C64 C65: library part C, "100V X7R 1210  4.7uF"
C22 C66: library part C, "100V X7R 1206  1uF"
C23 C26 C27 C63: library part C, "100V X7R 0805 100nF"
C28: "容值:22uF;精度:±20%;额定电压:100V;纹波电流:60mA@120Hz;", JLCPCB Part Class="Extended Part", LCSC Part Name="22uF ±20% 100V", Manufacturer=JIERR(捷而瑞), ManufacturerPart=JVJ100V22M6x8, Operating Temperature=-55℃~+105℃, Ripple Current=60mA@120Hz, Tolerance=±20%, Voltage Rating=100V
C31: "容值:220uF;精度:±20%;额定电压:25V;纹波电流:2.9A@100kHz;等效串联电阻(ESR):28mΩ@100kHz;类型:聚合物;", Equivalent Series Resistance(ESR)=28mΩ@100kHz, JLCPCB Part Class="Extended Part", LCSC Part Name="220uF ±20% 25V", Manufacturer=JIERR(捷而瑞), ManufacturerPart=MA25V220M6X8, Operating Temperature=-55℃~+105℃, Ripple Current=2.9A@100kHz, Tolerance=±20%, Voltage Rating=25V
C32: library part C, "25V X7R 0805 4.7uF"
C35: library part C, "16V X7R 0805 22uF"
C36 C37 C38 C39: library part C, "16V X7R 0805 4.7uF"
C47 C50: library part C, "6.3V X7R 0603 470nF"
C48 C51 C52: library part C, "6.3V X7R 0603 330pF"
C67: library part C, "100V X7R 0805  100nF"
CN1: "连接器类型:简牛座;间距:-;结构:2x10P;额定电流:3A;额定电压:250V;安装方式:直插;行距:2.54mm;排数:2;每排PIN数:10;触头材质:-;触头镀层:-;工作温度:-40℃~+105℃;", Current Rating=3A, JLCPCB Part Class="Extended Part", LCSC Part Name="2x10P 排数:2 每排P数:10", Manufacturer=XFCN(兴飞), ManufacturerPart=BH254V-20P, Operating Temperature=-40℃~+105℃, Voltage Rating (Max)=250V
D1 D2 D3 D4: "二极管配置:独立式;整流电流:150mA;直流反向耐压(Vr):100V;正向压降(Vf):1.25V@150mA;反向恢复时间(Trr):4ns;", Current - Rectified=150mA, JLCPCB Part Class="Extended Part", LCSC Part Name="100V 150mA", Manufacturer=R+O(宏嘉诚), ManufacturerPart=1N4148W, Non-Repetitive Peak Forward Surge Current=2A, Operating Junction Temperature Range=-55℃~+150℃, Pd - Power Dissipation=400mW, Reverse Leakage Current (Ir)=1uA@75V, Voltage - DC Reverse(Vr)=100V, Voltage - Forward(Vf@If)=1.25V@150mA
D5: "二极管配置:独立式;正向压降(Vf):850mV@3A;直流反向耐压(Vr):100V;整流电流:3A;", Current - Rectified=3A, JLCPCB Part Class="Extended Part", LCSC Part Name="电压:100V 电流:3A", Manufacturer=R+O(宏嘉诚), ManufacturerPart=SS310, Non-Repetitive Peak Forward Surge Current=80A, Operating Junction Temperature Range=-55℃~+150℃, Reverse Leakage Current (Ir)=50uA@100V, Voltage - DC Reverse(Vr)=100V, Voltage - Forward(Vf@If)=850mV@3A
L1: "电感值:15uH;精度:±20%;额定电流:30A;饱和电流(Isat):30.5A;类型:-;", Current - Saturation(Isat)=30.5A, Current Rating=30A, DC Resistance(DCR)=3.5mΩ, JLCPCB Part Class="Extended Part", LCSC Part Name="15uH ±20% 30.5A", Manufacturer=FC(方成), ManufacturerPart=FC-SE2822-150M, Ratings=-, Tolerance=±20%
L2: "电感值:47uH;精度:±20%;额定电流:1.5A;饱和电流(Isat):2A;类型:一体成型电感;", DC Resistance (DCR)=385mΩ, JLCPCB Part Class="Extended Part", LCSC Part Name="47uH ±20% 2A", Manufacturer=cjiang(长江微电), ManufacturerPart=FXL0630-470-M, Rated Current=1.5A, Saturation Current (Isat)=2A, Tolerance=±20%
L3: "电感值:4.7uH;精度:±20%;额定电流:2A;饱和电流(Isat):2.6A;类型:-;", Current - Saturation(Isat)=2.6A, Current Rating=2A, DC Resistance(DCR)=160mΩ, JLCPCB Part Class="Extended Part", LCSC Part Name="4.7uH ±20% 2.6A", Manufacturer=cjiang(长江微电), ManufacturerPart=FTC252010S4R7MBCA, Tolerance=±20%
L4: "阻抗@频率:600Ω@100MHz;误差:±25%;直流电阻(DCR):450mΩ;", Current Rating=200mA, DC Resistance(DCR)=450mΩ, Impedance @ Frequency=600Ω@100MHz, JLCPCB Part Class="Basic Part", LCSC Part Name="单路 0603磁珠 阻抗600Ω@100MHz", Manufacturer=Sunlord(顺络), ManufacturerPart=GZ1608D601TF, Operating Temperature=-55℃~+125℃, Tolerance=±25%
LED1 LED3 LED4: "灯头类型:-;发光颜色:红色;正向压降(Vf):1.6V~2.6V;功率:65mW;正向电流:25mA;波长:615nm~630nm;二极管配置:独立二极管;透镜颜色:-;色温:-;发光强度:195mcd;发光角度:130°;载带方式:-;工作温度:-30℃~+85℃;", Color Temperature=-, Forward Current=25mA, Illumination Color=红色, JLCPCB Part Class="Basic Part", LCSC Part Name=片式发光二极管, Manufacturer=国星光电, ManufacturerPart=NCD0805R1, Operating Temperature=-30℃~+85℃, Power(Watts)=65mW, Voltage - Forward(Vf)=1.6V~2.6V
Q1 Q2 Q3 Q4: "数量:1个N沟道;漏源电压(Vdss):100V;连续漏极电流(Id):80A;导通电阻(RDS(on)):10.5mΩ@4.5V;耗散功率(Pd):100W;阈值电压(Vgs(th)):2.5V;", Current - Continuous Drain(Id)=80A, Drain To Source Voltage=100V, Gate Threshold Voltage (Vgs(th))=2.5V, Input Capacitance(Ciss)=3.15nF, JLCPCB Part Class="Extended Part", LCSC Part Name="1个N沟道 耐压:100V 电流:80A", Manufacturer=CJ(江苏长电/长晶), ManufacturerPart=CJAC80SN10, Operating Temperature=-55℃~+150℃, Output Capacitance(Coss)=650pF, Pd - Power Dissipation=100W, Reverse Transfer Capacitance (Crss@Vds)=8pF
R1 R3 R4 R5 R6 R7 R9 R10 R11 R12 R13 R15 R16 R17 R18 R19 R20 R21 R22 R23 R24 R25 R26 R27 R28 R29 R30 R31 R32 R33 R34 R35 R36 R37 R38 R39 R40 R41 R42 R43 R44 R45 R46 R47 R48 R49 R56 R58 R59 R61 R62: library part R, "贴片电阻"
R8 R14: "电阻类型:采样电阻;阻值:5mΩ;精度:±1%;功率:3W;安装方式:贴片;", JLCPCB Part Class="Extended Part", LCSC Part Name="5mΩ ±1% 3W", Manufacturer=Milliohm(毫欧), ManufacturerPart=HoJLR2512-3W-5mR-1%, Power(Watts)=3W, Tolerance=±1%
R55 R57: library part R, "贴片电阻NTC"
SW1: "电路结构:单刀单掷;按钮形状:矩形按钮;作用力:2.6N;安装方式:立贴;开关长度:6mm;开关宽度:3.6mm;开关高度:2.5mm;带支架:不带支架;触点电流:50mA;额定电压:12V;带灯:无;工作寿命:5万次;", Actuator/Cap Color=-, Contact Current=50mA, JLCPCB Part Class="Extended Part", LCSC Part Name="6*3.6*2.5mm 立贴 轻触开关", Manufacturer="XKB Connection(中国星坤)", ManufacturerPart=TS-1101-C-W, Operating Force=2.6N, Operating Temperature=-30℃~+85℃, Voltage Rating=12V
U1: "插针结构:1x6P;间距:2.5mm;安装方式:直插;参考系列:XH;总PIN数:6P;排数:1;每排PIN数:6;行距:-;额定电流:3A;触头材质:黄铜;触头镀层:锡;工作温度:-25℃~+85℃;", Color=白色, Current Rating=3A, Flame Retardant Rating=UL94V-0, JLCPCB Part Class="Extended Part", LCSC Part Name="1x6P 间距:2.5mm 直插 系列:XH", Manufacturer=Megastar(兆星), ManufacturerPart=ZX-XH2.54-6PZZ, Operating Temperature=-25℃~+85℃, Voltage Rating=250V
U2 U3: library part CMP-04912-000066-1, "IC GATE DRVR HALF-BRIDGE 8SOPWR", Case/Package=HSOP, Max Operating Temperature=140°C, Max Output Current=4.5A, Max Supply Current=4.3mA, Max Supply Voltage=17V, Min Operating Temperature=-40°C, Min Supply Voltage=8V, Nominal Supply Current=4A, Operating Supply Voltage=12V, Package Quantity=1
U4: "功能类型:降压型;工作电压:10V~100V;输出电压:-;输出电流:3A;输出类型:可调;", Frequency - Switching=110kHz, JLCPCB Part Class="Extended Part", LCSC Part Name="降压型 3A 10V~100V", Manufacturer=EG(屹晶微), ManufacturerPart=EG1192L, Operating Temperature=-45℃~+125℃, Output Current=3A, Output Voltage=-, Quiescent Current=2mA, Voltage - Supply=10V~100V
U5: "功能类型:降压型;工作电压:4.5V~18V;输出电压:-;输出电流:2A;输出类型:可调;", Frequency - Switching=500kHz, JLCPCB Part Class="Extended Part", LCSC Part Name="降压型 2A 4.5V~18V", Manufacturer=Silergy(矽力杰), ManufacturerPart=SY8120B1ABC, Operating Temperature=-40℃~+85℃@(TA), Output Current=2A, Output Voltage=-, Quiescent Current=400uA, Voltage - Supply=4.5V~18V
U6 U7: "输出极性:正极;工作电压:5.5V;输出电压:3.3V;输出电流:500mA;电源纹波抑制比(PSRR):50dB@(10kHz);输出类型:固定;", JLCPCB Part Class="Extended Part", LCSC Part Name="3.3V 500mA 5.5V", Manufacturer=RICHTEK(立锜), ManufacturerPart=RT9013-33GB, Operating Temperature=-40℃~+125℃@(Tj), Output Current=500mA, Output Voltage=3.3V, Power Supply Rejection Ratio (PSRR)=50dB@(10kHz), standby current=25uA, Voltage - Supply=5.5V, Voltage Dropout=400mV@(500mA)
U8 U9: "放大器数:双路;增益带宽积(GBP):13MHz;输入偏置电流(Ib):100pA;输入失调电压(Vos):5uV;压摆率(SR):8V/us;轨到轨:轨到轨输入,轨到轨输出;", Ib - Input Bias Current=100pA, Input Offset Current(Ios)=10pA, Input Offset Voltage Drift(Vos TC)=27nV/℃, JLCPCB Part Class="Extended Part", LCSC Part Name=带射频滤波器的零漂移CMOS轨到轨输入输出运算放大器, Manufacturer=Gainsil(聚洵), ManufacturerPart=GS8558-SR, Maximum Power Supply Range (Vdd-Vss)=5.5V, Operating Temperature=-40℃~+125℃, Output Current=109mA, Quiescent Current(Iq)=1.3mA, Vos - Input Offset Voltage=5uV
U10 U11 U12 U13: JLCPCB Part Class="Extended Part", LCSC Part Name="四脚 M3 二件套 T34001", Manufacturer=XFCN(兴飞), ManufacturerPart=T34001
U14: "CPU内核:ARM Cortex-M4F;CPU最大主频:170MHz;CPU位数:32 Bit;", JLCPCB Part Class="Extended Part", LCSC Part Name="带DSP和FPU的170MHz主流ARM Cortex-M4 MCU，具有128 KB Flash存储器、数学加速器、高分辨率定时器和高模拟电平集成", Manufacturer=ST(意法半导体), ManufacturerPart=STM32G474RBT3, Operating Temperature=-40℃~+125℃, Voltage - Supply=1.71V~3.6V
U15: "接口类型:I2C;存储容量:512Kbit;时钟频率(fc):1MHz;", Clock Frequency=1MHz, JLCPCB Part Class="Extended Part", LCSC Part Name=兼容I²C（两线制）的串行EEPROM, Manufacturer=MICROCHIP(美国微芯), ManufacturerPart=AT24C512C-SSHD-T, Operating Temperature=-40℃~+85℃, Voltage - Supply=2.5V~5.5V
X1: "晶振类型:贴片晶振;频率:24MHz;常温频差:±10ppm;负载电容:12pF;频率稳定度:±20ppm;", Equivalent Series Resistance(ESR)=100Ω, Frequency Stability=±20ppm, JLCPCB Part Class="Extended Part", LCSC Part Name="YSX221SL 24MHZ 12PF ±10PPM -40~85℃ (±20PPM）", Load Capacitance=12pF, Manufacturer=YXC(扬兴晶振), ManufacturerPart=X252024MOB4SI, Normal temperature Frequency Tolerance=±10ppm, Operating Temperature=-40℃~+85℃

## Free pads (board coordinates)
  round 40 smd: 2(1290,1310) 2(1680,2320) 2(2120,1505) 2(2251.24,1406.61) 2(2830,1375)

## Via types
v1: diameter 23.62, hole 11.81, Top Layer to Bottom Layer, tented both sides, 276 vias
v2: diameter 39.37, hole 19.68, Top Layer to Bottom Layer, tented both sides, 113 vias
v3: diameter 47.24, hole 27.56, Top Layer to Bottom Layer, tented both sides, 2 vias

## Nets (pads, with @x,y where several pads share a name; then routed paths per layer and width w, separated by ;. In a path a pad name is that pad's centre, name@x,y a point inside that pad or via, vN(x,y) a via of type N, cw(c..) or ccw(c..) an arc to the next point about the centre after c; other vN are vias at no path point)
+3.3V: C4.2 C7.2 C37.2 C56.2 C57.2 C58.2 C59.2 C71.2 CN1.1 CN1.2 R1.1 R22.2 R45.2 R46.2 R47.2 R49.1 R62.2 U6.5 U14.1 U14.16 U14.32 U14.48 U14.64 U15.8 | length 4094.7
  Top Layer w15: R49.1@3324.41,505 3357.09,472.32 3357.09,392.91 v1(3385,365) ; C71.2@3393.09,377.5 3409.54,377.5 3423.93,363.11 3455.31,363.11 U14.64@3455.59,362.83 ; v1(3460,300) 3462.33,300 3476.28,286.06 U14.1@3532.36,286.06 ; v1(3500,790) 3501.65,788.35 3501.65,785.09 3532.36,754.38 U14.48@3532.36,733.94 ; U14.16@3827.64,286.06 3829.23,284.46 3829.23,231.95 C58.2@3831.18,230 ; U14.32@3904.41,658.11 3908.41,658.11 3910,659.7 3910,680 3921.18,691.18 v1(3970,691.18)
  Top Layer w25: U6.5@2865,640.25 2867.85,637.4 U6.5@2875.5,637.4
  Top Layer w40: U15.8@3917.37,965 3925.79,956.58 3969.02,956.58 C4.2@3985,940.59 ; v1(3970,691.18) R1.1@4035,691.18
  Layer 2 w35: v1(2535,330) 2545,320 2874.41,320 v1(2879.41,325) 2889.41,315 3095,315 v1(3105,325) 3195,325 3225,295 ; CN1.2@3225,155 CN1.1@3225,255
  Layer 2 w40: v1(3190,785) v1(3325,785) 3330,790 v1(3500,790) 3890,790 ; CN1.1@3235.43,255 3235.43,287 3243.43,295 3390,295 ; v1(3385,365) 3390,360 3390,295 ; v1(3940,965) 3890,915 3890,790 ; 3390,295 3465,295 3535,225 v1(3845,225) 3890,225 4120,455 4120,665 4093.82,691.18 v1(3970,691.18) 3970,710 3890,790
  Bottom Layer w40: R45.2@3221.18,330 3221.18,258.82 CN1.1@3225,255
  other v1: 3025,590 3270,785
+3.3Vsense: C2.2 C3.2 C39.2 C47.1 C50.1 R23.1 R55.2 R57.2 U7.5 U8.8 U9.8 U14.29 | length 8738.9
  Top Layer w10: U8.8@758.3,1155 835,1155 C47.1@840,1160
  Top Layer w12: v1(3860,600) 3860.86,599.14 3904.32,599.14 U14.29@3904.41,599.05
  Top Layer w30: U7.5@2875.5,907.4 C39.2@2950,907.4 2957.5,907.4 3070.1,1020 3755,1020 3795,1060 ; C50.1@4030,1254.41 4025.59,1250 U9.8@3954.2,1250 3950.75,1246.55 3891.55,1246.55 3820,1175 3820,1085 3795,1060 ; R23.1@4035,509.41 4139.41,509.41 4220,590 4220,769.71 3994,995.71 3994,996 3930,1060 3795,1060
  Layer 2 w30: v1(2675,2365) 3335,2365 3470,2230 3470,1340 3067.46,937.46 v2(2988.24,937.46)
  Bottom Layer w15: v1(860,1160) 945,1160 1085,1020 1620,1020 ; v1(1630,2340) 1630,2280 1668.5,2241.5 1668.5,2073.5 1620,2025 1620,1020 ; v2(2988.24,937.46) 2367.54,937.46 2285,1020 1620,1020
  Bottom Layer w30: v1(3860,600) 3890.59,569.41 C2.2@3970,569.41 3975.59,575 v1(4195,575)
+5V: C35.1 C36.2 L3.2 L4.1 R20.1 R61.2 U1.5 U6.1 U6.3 | length 2302.3
  Top Layer w10: R61.2@2210,970 2212.4,967.6 R20.1@2212.4,890 2415,890 2440,865 C35.1@2440,637.4
  Top Layer w25: U6.3@2784.6,562.6 2815.36,562.6 2830,577.24 2830,619.91 2815.36,634.55 2787.45,634.55 U6.1@2784.6,637.4
  Layer 2 w40: U1.5@1373.14,140 1368.74,144.41 1368.74,160.66 1365,164.39 1365,405 1620,660 v1(2600,660)
+12V: C11.2 C12.2 C13.2 C14.2 C30.2 C31.1 C32.2 C33.2 L2.2 R17.2 R21.1 R59.2 U2.1 U3.1 U5.5 | length 3437.4
  Top Layer w10: R17.2@1217.4,280 1217.4,273.28 1229.9,260.78 1259.22,260.78 1305,215 1735,215 1805,285 1805,489.9 1847.5,532.4 C30.2@1855,532.4 ; R59.2@1387.6,965 1387.6,812.4 1455,745 1610,745 1635,720 C31.1@1635,555.1
  Top Layer w60: U2.1@1726.18,1430 1733.07,1423.11 C14.2@1733.07,1389.32 ; C14.2@1742.4,1370 v1(1742.4,1295) 1742.4,1257.6 1970,1030 1970,820 1860,710 1855,710 C30.2@1855,532.4 ; 2380,1555 2455.81,1555 2485,1525.81 2485,1525
  Bottom Layer w60: v1(1742.4,1295) 2007.4,1560 C12.2@2392.6,1560 ; C12.2@2387.6,1560 C12.2@2395,1552.6
  other v1: 2420,1557.4
BOOT0: R24.2 R49.2 U14.61 | length 139.6
  Top Layer w15: R49.2@3385.59,505 3385.59,445 3408.71,421.88 U14.61@3455.59,421.88
EPWM1A: U3.6 U14.42 | length 1700.9
  Top Layer w6: U14.42@3650.47,733.94 3650.47,644.9 3665,630.37 v1(3665,630)
  Layer 2 w6: v1(2690,1410) 2765,1335 2765,905 2929,741 3624,741 3665,700 v1(3665,630)
EPWM1B: U3.5 U14.43 | length 1619
  Top Layer w6: v1(3625,635) 3625,639.77 3630.79,645.56 U14.43@3630.79,733.94
  Layer 2 w6: v1(2675,1355) 2735,1295 2735,875 2895,715 3585,715 3625,675 v1(3625,635)
EPWM2A: U2.5 U14.44 | length 2593.4
  Top Layer w6: v1(3570,645) 3584.74,659.74 3599.74,659.74 3611.1,671.1 U14.44@3611.1,733.94
  Layer 2 w6: v1(1515,1580) 1575,1580 2375,780 2560,780 2645,695 3553.67,695 3586.74,661.94 3586.74,656.97 3574.77,645 v1(3570,645)
EPWM2B: U2.6 U14.45 | length 2504.9
  Top Layer w6: v1(3549.62,669.62) 3550,670 3576.26,670 3591.42,685.16 U14.45@3591.42,733.94
  Layer 2 w6: 1528.37,1531.63 1518.37,1531.63 v1(1515,1535) 1554.87,1535 2339.87,750 2551.01,750 2630.2,670.81 3548.43,670.81 v1(3549.62,669.62)
FAULT: U1.4 U14.58 | length 2299.8
  Top Layer w6: U14.58@3455.59,480.93 3515.94,480.93 v1(3535,500)
  Layer 2 w6: U1.4@1471.57,140 1576.57,245 1760,245 1955,440 2375,440 2435,500 v1(3535,500)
